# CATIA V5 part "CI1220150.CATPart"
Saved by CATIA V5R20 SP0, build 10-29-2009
Part number: CI1220150
Bounding box of the stored display mesh (mm): x -21.949 to 22.289, y -19 to 19, z -150 to 45.368
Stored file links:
  C:\Users\Raffaele\Desktop\3D X SITO CF\BOLEX\19-INCLINED ASSEMBLY REF_CI\CI1220150.CATPart

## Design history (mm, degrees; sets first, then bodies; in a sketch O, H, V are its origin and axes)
Set1
  DatumSurface1 to DatumSurface16 "MANIFOLD_SOLID_BREP #387"
  DatumSurface17 to DatumSurface39 "MANIFOLD_SOLID_BREP #1116"
Body1 (main body)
